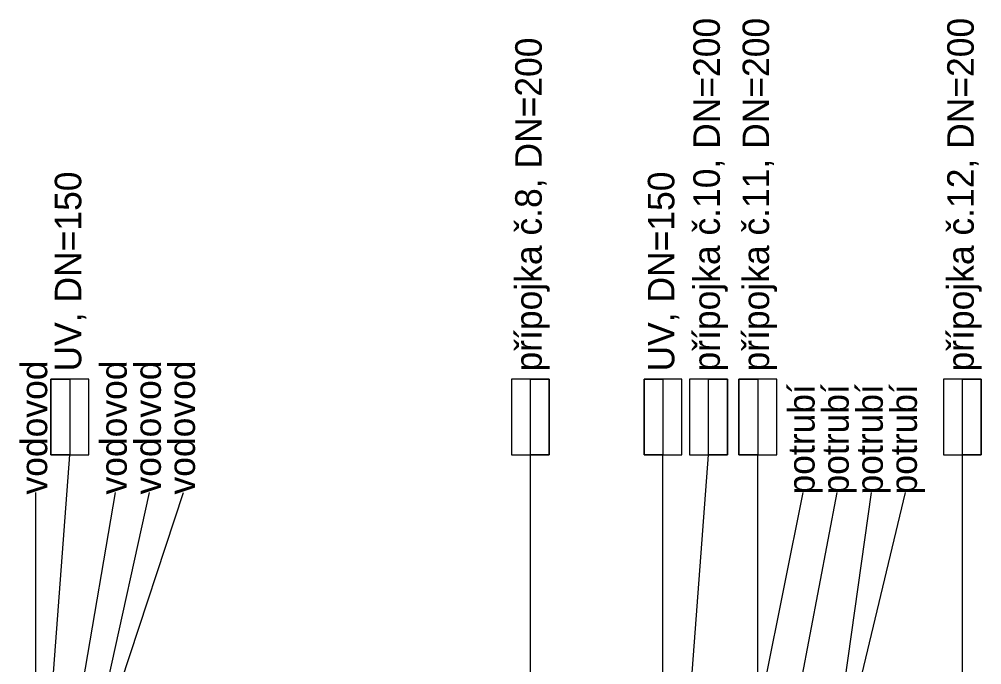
# Model space of a CAD drawing. Extents: x -760612 to 2731, y -975740 to 2995.
# Drawn here: x -228 to 280, y 1953 to 2294 of the extents above; entities that cross this region are included whole.
import ezdxf

# ---------------------------------------------------------------- set-up
doc = ezdxf.new("R2010")
doc.units = 0
doc.layers.add('INVESTICE', color=7, linetype='Continuous')
doc.layers.add('KANAL_VLOZKY', color=7, linetype='Continuous')

msp = doc.modelspace()

# ---------------------------------------------------------------- linework, layer by layer
at = {"layer": 'INVESTICE'}
for p, q in [((-219.11, 1944.34), (-219.11, 2044.34)), ((-194.11, 1944.34), (-177.11, 2044.34)), ((-181.11, 1944.34), (-159.11, 2044.34)), ((-174.11, 1944.34), (-141.11, 2044.34)), ((165.89, 1944.34), (185.89, 2044.34)), ((184.89, 1944.34), (203.89, 2044.34)), ((207.89, 1944.34), (221.89, 2044.34)), ((215.89, 1944.34), (239.89, 2044.34))]:
    msp.add_line(p, q, dxfattribs=at)
at = {"layer": 'KANAL_VLOZKY'}
for p, q in [((-191.11, 2104.34), (-211.11, 2104.34)), ((-211.11, 2104.34), (-211.11, 2064.34)), ((-191.11, 2064.34), (-191.11, 2104.34)), ((51.89, 2104.34), (31.89, 2104.34)), ((31.89, 2104.34), (31.89, 2064.34)), ((51.89, 2064.34), (51.89, 2104.34)), ((121.89, 2104.34), (101.89, 2104.34)), ((101.89, 2104.34), (101.89, 2064.34)), ((121.89, 2064.34), (121.89, 2104.34)), ((145.89, 2104.34), (125.89, 2104.34)), ((125.89, 2104.34), (125.89, 2064.34)), ((145.89, 2064.34), (145.89, 2104.34)), ((171.89, 2104.34), (151.89, 2104.34)), ((151.89, 2104.34), (151.89, 2064.34)), ((171.89, 2064.34), (171.89, 2104.34)), ((279.89, 2104.34), (259.89, 2104.34)), ((259.89, 2104.34), (259.89, 2064.34)), ((279.89, 2064.34), (279.89, 2104.34)), ((-211.11, 2064.34), (-191.11, 2064.34)), ((-210.11, 1944.34), (-201.11, 2064.34)), ((31.89, 2064.34), (51.89, 2064.34)), ((41.89, 1944.34), (41.89, 2064.34)), ((101.89, 2064.34), (121.89, 2064.34)), ((111.89, 1944.34), (111.89, 2064.34)), ((125.89, 2064.34), (145.89, 2064.34)), ((126.89, 1944.34), (135.89, 2064.34)), ((151.89, 2064.34), (171.89, 2064.34)), ((161.89, 1944.34), (161.89, 2064.34)), ((259.89, 2064.34), (279.89, 2064.34)), ((269.89, 1944.34), (269.89, 2064.34))]:
    msp.add_line(p, q, dxfattribs=at)
for points in [[(-211.11, 2104.34), (-201.11, 2104.34), (-201.11, 2064.34), (-211.11, 2064.34)], [(41.89, 2104.34), (51.89, 2104.34), (51.89, 2064.34), (41.89, 2064.34)], [(101.89, 2104.34), (111.89, 2104.34), (111.89, 2064.34), (101.89, 2064.34)], [(135.89, 2104.34), (145.89, 2104.34), (145.89, 2064.34), (135.89, 2064.34)], [(151.89, 2104.34), (161.89, 2104.34), (161.89, 2064.34), (151.89, 2064.34)], [(269.89, 2104.34), (279.89, 2104.34), (279.89, 2064.34), (269.89, 2064.34)]]:
    msp.add_lwpolyline(points, close=True, dxfattribs=at)

# ---------------------------------------------------------------- texts
at = {"layer": 'INVESTICE'}
for s, p in [('vodovod', (-213.11, 2043.34)), ('vodovod', (-171.11, 2043.34)), ('vodovod', (-153.11, 2043.34)), ('vodovod', (-135.11, 2043.34)), ('potrubí', (191.89, 2043.34)), ('potrubí', (209.89, 2043.34)), ('potrubí', (227.89, 2043.34)), ('potrubí', (245.89, 2043.34))]:
    msp.add_text(s, height=14, rotation=90, dxfattribs=at).set_placement(p)
at = {"layer": 'KANAL_VLOZKY'}
for s, p in [('přípojka č.10, DN=200', (141.89, 2108.34)), ('přípojka č.11, DN=200', (167.89, 2108.34)), ('přípojka č.12, DN=200', (275.89, 2108.34)), ('přípojka č.8, DN=200', (47.89, 2108.34)), ('UV, DN=150', (-195.11, 2108.34)), ('UV, DN=150', (117.89, 2108.34))]:
    msp.add_text(s, height=14, rotation=90, dxfattribs=at).set_placement(p)

doc.saveas('drawing.dxf')
